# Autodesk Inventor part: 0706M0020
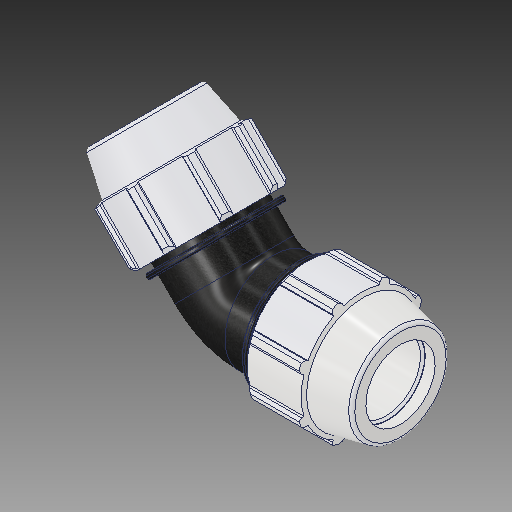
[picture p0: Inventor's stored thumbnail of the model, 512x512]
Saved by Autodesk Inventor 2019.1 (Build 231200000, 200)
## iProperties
Created: 2017-02
Part Number: 0706M0020
Material: PVC-Piping
Description: PLASSON 45° ELBOW 2'' - 2''
Document SubType Name: Modeling
Designer: KIM
Mass: 92.6774 g
Surface Area: 199.44 cm^2
Volume: 66.1981 cm^3
Density: 1.4 g/cm^3
Appearance: PTFE
Author: KIM
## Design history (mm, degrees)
derived "0706M0.ipt"
feature "Solid1::0706M0.ipt"
tag "TaggingFeature1"
body "Solid1"
other parameters: "d2" = 60.1, "d4" = 10.83733, "d5" = 32.512, "d7" = 113.03, "d9" = 18.57829, "d11" = 4.33493, "d13" = 120 deg, "d14" = 84.14, "d15" = 12 deg, "d16" = 98.3361, "d18" = 3.005, "d19" = 35 deg, "d20" = 17.5 deg, "d21" = 105.1179, "d23" = 0, "d25" = 360 deg, "d27" = 2.2606, "d33" = 1.202, "d42" = 48.11776, "d43" = 3.3909, "d46" = 1.803, "d51" = 130.048, "d59" = 135 deg, "d63" = 109.982, "d67" = 84.7725, "d68" = 4.33493, "d72" = 1.5, "d73" = 0, "d74" = 0, "d_" = 60.1, "E_" = 113.03, "A_" = 130.048, "l_" = 109.982
